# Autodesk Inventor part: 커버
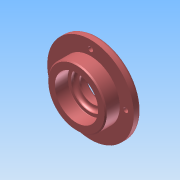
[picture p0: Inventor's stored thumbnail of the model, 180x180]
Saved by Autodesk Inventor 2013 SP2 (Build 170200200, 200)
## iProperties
Created: 2026-07
Part Number: 커버
Material: Generic
Document SubType Name: Modeling
Designer: 601
Density: 1 g/cm^3
Author: 601
변환 표준: STEP AP214IS
전처리기: Build: 200, Release: 2013 SP2 Update 6 - Date: Thu 07/17/2014
전송 단위: 밀리미터
불확실성: 0.01
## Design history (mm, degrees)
node "커버1"
node "솔리드1"
node "기준1"
